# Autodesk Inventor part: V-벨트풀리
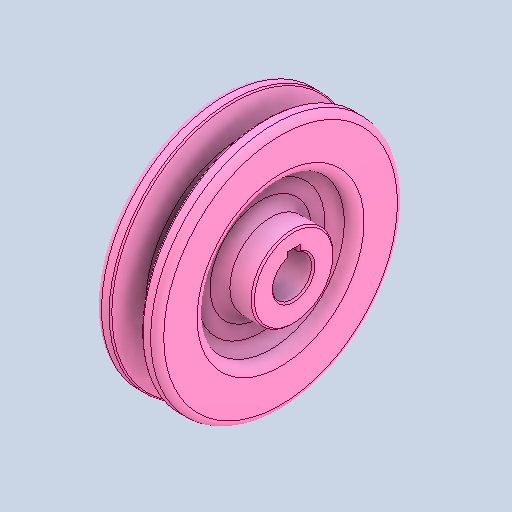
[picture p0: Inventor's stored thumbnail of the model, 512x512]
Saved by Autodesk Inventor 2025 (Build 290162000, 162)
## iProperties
Created: 2024-07
Part Number: V-벨트풀리
Material: 강철, 탄소
Document SubType Name: Modeling
Designer: hsj03
Density: 7.87 g/cm^3
Appearance: 기본값
Author: jhkim
Sending System: Autodesk Inventor 2025
Preprocessor: ST-DEVELOPER v20
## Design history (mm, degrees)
feature "솔리드1"
node "솔리드2"
